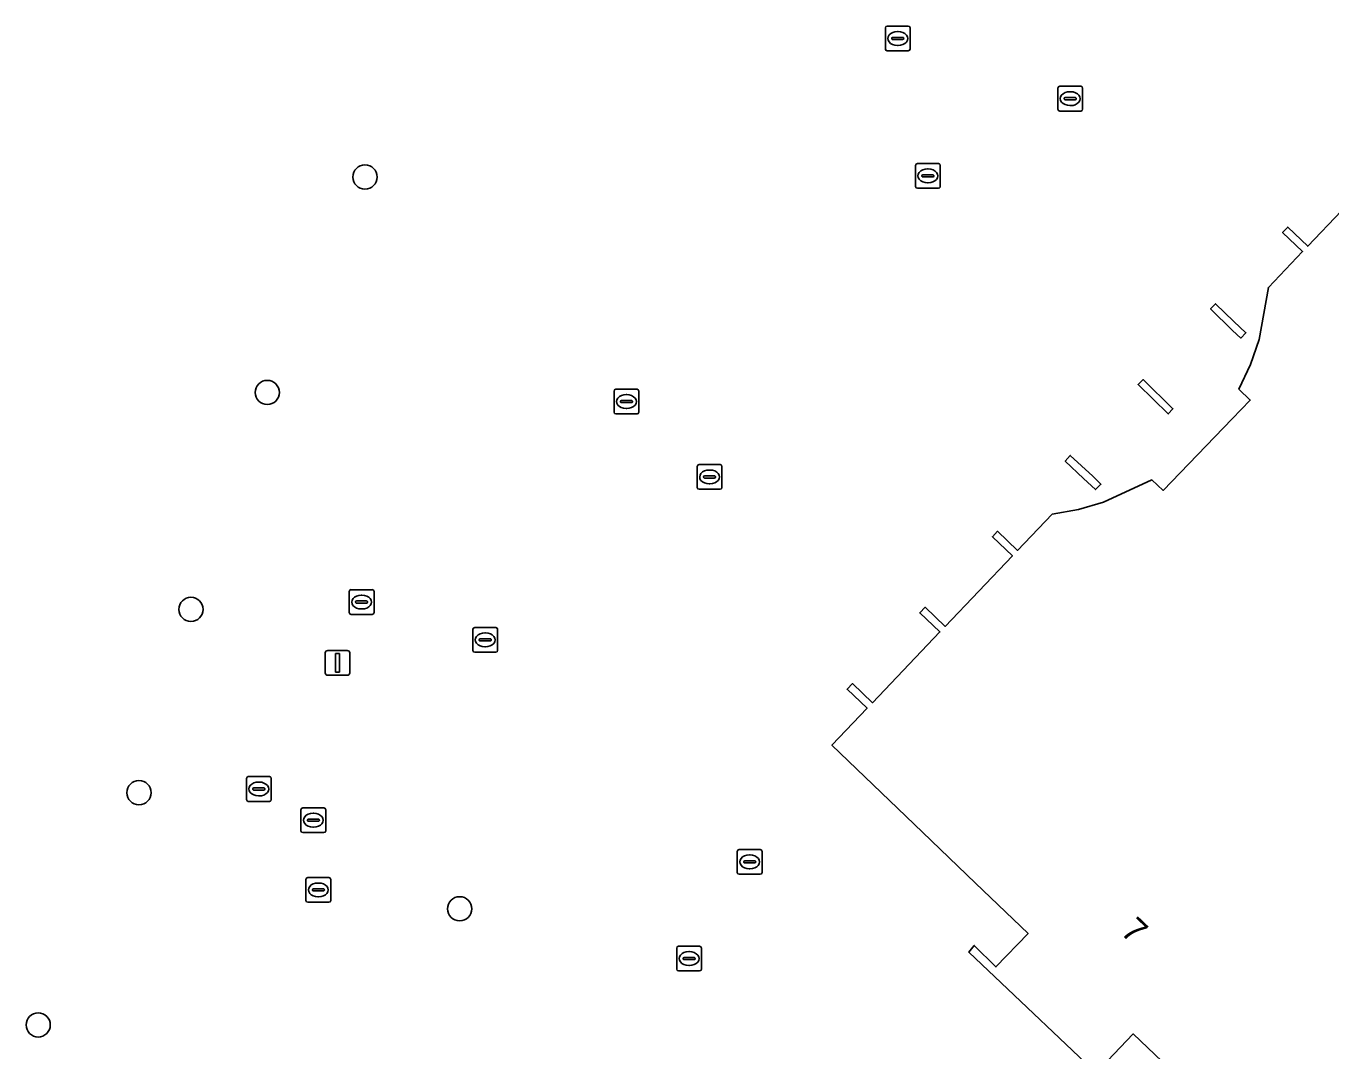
# Model space of a CAD drawing. Extents: x 156061 to 157804, y 383437 to 385640.
# Drawn here: x 156716.3 to 156769, y 385081.3 to 385122.7 of the extents above; entities that cross this region are included whole.
import ezdxf

# ---------------------------------------------------------------- set-up
doc = ezdxf.new("R2010")
doc.units = 0
for name, color, linetype in [('IMGEO_Boom', 7, 'Continuous'), ('IMGEO_Erf', 7, 'Continuous'), ('IMGEO_Kolk', 7, 'Continuous'), ('IMGEO_Lichtmast', 7, 'Continuous'), ('IMGEO_Pand', 7, 'Continuous'), ('IMGEO_Pand_nummerreeks', 7, 'Continuous'), ('IMGEO_Rioolput', 7, 'Continuous')]:
    doc.layers.add(name, color=color, linetype=linetype)

msp = doc.modelspace()

# ---------------------------------------------------------------- linework, layer by layer
at = {"layer": 'IMGEO_Boom'}
for centre in [(156730.004, 385116.568), (156726.055, 385107.866), (156722.969, 385099.103), (156720.871, 385091.698), (156733.83, 385087.008), (156716.798, 385082.318)]:
    msp.add_circle(centre, 0.489, dxfattribs=at)
at = {"layer": 'IMGEO_Erf'}
for points in [[(156760.425, 385079.549), (156754.405, 385085.261), (156754.626, 385085.527), (156755.503, 385084.662), (156756.803, 385086.009), (156754.676, 385088.049), (156752.53, 385090.107), (156748.874, 385093.614), (156750.296, 385095.106), (156749.486, 385095.879), (156749.699, 385096.103), (156750.509, 385095.33), (156753.234, 385098.19), (156752.424, 385098.963), (156752.638, 385099.187), (156753.448, 385098.414), (156756.166, 385101.267), (156755.356, 385102.04), (156755.563, 385102.257), (156756.373, 385101.484), (156757.769, 385102.949), (156758.836, 385103.138), (156759.851, 385103.431), (156761.8, 385104.331), (156762.254, 385103.908), (156762.945, 385104.624), (156765.052, 385106.806), (156765.778, 385107.557), (156765.322, 385107.998), (156765.792, 385108.99), (156766.141, 385110), (156766.514, 385112.109), (156767.894, 385113.558), (156767.083, 385114.331), (156767.29, 385114.548), (156768.101, 385113.775), (156770.825, 385116.635)], [(156768.968, 385074.402), (156761.046, 385081.957), (156759.76, 385080.603)]]:
    msp.add_lwpolyline(points, dxfattribs=at)
for points in [[(156765.401, 385110.061), (156765.065, 385110.37), (156764.175, 385111.241), (156764.37, 385111.451), (156765.12, 385110.733), (156765.605, 385110.279)], [(156761.243, 385108.182), (156761.444, 385108.383), (156762.656, 385107.209), (156762.467, 385106.999)], [(156758.303, 385105.094), (156758.501, 385105.323), (156759.413, 385104.478), (156759.74, 385104.157), (156759.526, 385103.94), (156759.041, 385104.39)]]:
    msp.add_lwpolyline(points, close=True, dxfattribs=at)
at = {"layer": 'IMGEO_Kolk'}
for p, q in [((156758.003, 385119.308), (156758.003, 385120.16)), ((156758.078, 385120.234), (156758.93, 385120.234)), ((156758.491, 385120.014), (156758.516, 385120.014)), ((156759.004, 385120.16), (156759.004, 385119.308)), ((156758.262, 385119.728), (156758.262, 385119.74)), ((156758.7, 385119.691), (156758.302, 385119.691)), ((156758.305, 385119.777), (156758.703, 385119.777)), ((156758.514, 385119.454), (156758.489, 385119.454)), ((156758.746, 385119.74), (156758.746, 385119.728)), ((156758.93, 385119.234), (156758.078, 385119.234)), ((156740.07, 385107.071), (156740.07, 385107.923)), ((156740.145, 385107.997), (156740.997, 385107.997)), ((156740.558, 385107.777), (156740.583, 385107.777)), ((156741.071, 385107.923), (156741.071, 385107.071)), ((156740.329, 385107.491), (156740.329, 385107.503)), ((156740.767, 385107.454), (156740.369, 385107.454)), ((156740.372, 385107.54), (156740.77, 385107.54)), ((156740.581, 385107.217), (156740.556, 385107.217)), ((156740.813, 385107.503), (156740.813, 385107.491)), ((156740.997, 385106.997), (156740.145, 385106.997)), ((156743.429, 385104.027), (156743.429, 385104.879)), ((156743.504, 385104.953), (156744.356, 385104.953)), ((156743.917, 385104.733), (156743.942, 385104.733)), ((156744.43, 385104.879), (156744.43, 385104.027)), ((156743.688, 385104.447), (156743.688, 385104.459)), ((156744.126, 385104.41), (156743.728, 385104.41)), ((156743.731, 385104.496), (156744.129, 385104.496)), ((156743.94, 385104.173), (156743.915, 385104.173)), ((156744.172, 385104.459), (156744.172, 385104.447)), ((156744.356, 385103.953), (156743.504, 385103.953)), ((156725.214, 385091.422), (156725.214, 385092.274)), ((156725.289, 385092.348), (156726.141, 385092.348)), ((156725.516, 385091.891), (156725.914, 385091.891)), ((156725.702, 385092.128), (156725.727, 385092.128)), ((156726.215, 385092.274), (156726.215, 385091.422)), ((156726.141, 385091.348), (156725.289, 385091.348)), ((156725.473, 385091.842), (156725.473, 385091.854)), ((156725.911, 385091.805), (156725.513, 385091.805)), ((156725.725, 385091.568), (156725.7, 385091.568)), ((156725.957, 385091.854), (156725.957, 385091.842)), ((156745.049, 385088.477), (156745.049, 385089.329)), ((156745.124, 385089.403), (156745.976, 385089.403)), ((156746.05, 385089.329), (156746.05, 385088.477)), ((156745.308, 385088.897), (156745.308, 385088.909)), ((156745.746, 385088.86), (156745.348, 385088.86)), ((156745.351, 385088.946), (156745.749, 385088.946)), ((156745.537, 385089.183), (156745.562, 385089.183)), ((156745.792, 385088.909), (156745.792, 385088.897)), ((156727.619, 385087.344), (156727.619, 385088.196)), ((156727.694, 385088.27), (156728.546, 385088.27)), ((156728.62, 385088.196), (156728.62, 385087.344)), ((156745.976, 385088.403), (156745.124, 385088.403)), ((156745.56, 385088.623), (156745.535, 385088.623)), ((156727.878, 385087.764), (156727.878, 385087.776)), ((156728.316, 385087.727), (156727.918, 385087.727)), ((156727.921, 385087.813), (156728.319, 385087.813)), ((156728.107, 385088.05), (156728.132, 385088.05)), ((156728.362, 385087.776), (156728.362, 385087.764)), ((156728.546, 385087.27), (156727.694, 385087.27)), ((156728.13, 385087.49), (156728.105, 385087.49)), ((156742.6, 385084.571), (156742.6, 385085.423)), ((156742.675, 385085.497), (156743.527, 385085.497)), ((156742.902, 385085.04), (156743.3, 385085.04)), ((156743.088, 385085.277), (156743.113, 385085.277)), ((156743.601, 385085.423), (156743.601, 385084.571)), ((156743.527, 385084.497), (156742.675, 385084.497)), ((156742.859, 385084.991), (156742.859, 385085.003)), ((156743.297, 385084.954), (156742.899, 385084.954)), ((156743.111, 385084.717), (156743.086, 385084.717)), ((156743.343, 385085.003), (156743.343, 385084.991))]:
    msp.add_line(p, q, dxfattribs=at)
for points in [[(156758.003, 385119.308), (156758.003, 385120.16)], [(156758.078, 385120.234), (156758.93, 385120.234)], [(156759.004, 385120.16), (156759.004, 385119.308)], [(156758.93, 385119.234), (156758.078, 385119.234)], [(156740.07, 385107.071), (156740.07, 385107.923)], [(156740.145, 385107.997), (156740.997, 385107.997)], [(156741.071, 385107.923), (156741.071, 385107.071)], [(156740.997, 385106.997), (156740.145, 385106.997)], [(156743.429, 385104.027), (156743.429, 385104.879)], [(156743.504, 385104.953), (156744.356, 385104.953)], [(156744.43, 385104.879), (156744.43, 385104.027)], [(156744.356, 385103.953), (156743.504, 385103.953)], [(156725.214, 385091.422), (156725.214, 385092.274)], [(156725.289, 385092.348), (156726.141, 385092.348)], [(156726.215, 385092.274), (156726.215, 385091.422)], [(156726.141, 385091.348), (156725.289, 385091.348)], [(156745.049, 385088.477), (156745.049, 385089.329)], [(156745.124, 385089.403), (156745.976, 385089.403)], [(156746.05, 385089.329), (156746.05, 385088.477)], [(156727.619, 385087.344), (156727.619, 385088.196)], [(156727.694, 385088.27), (156728.546, 385088.27)], [(156728.62, 385088.196), (156728.62, 385087.344)], [(156745.976, 385088.403), (156745.124, 385088.403)], [(156728.546, 385087.27), (156727.694, 385087.27)], [(156742.6, 385084.571), (156742.6, 385085.423)], [(156742.675, 385085.497), (156743.527, 385085.497)], [(156743.601, 385085.423), (156743.601, 385084.571)], [(156743.527, 385084.497), (156742.675, 385084.497)]]:
    msp.add_lwpolyline(points, dxfattribs=at)
for centre, radius, start, end in [((156758.08, 385120.158), 0.0765, 91.552, 178.448), ((156758.08, 385120.158), 0.0765, 91.552, 178.448), ((156758.928, 385120.158), 0.0765, 1.552, 88.448), ((156758.928, 385120.158), 0.0765, 1.552, 88.448), ((156758.08, 385119.31), 0.0765, 181.552, 268.448), ((156758.08, 385119.31), 0.0765, 181.552, 268.448), ((156758.302, 385119.737), 0.0403, 85.8775, 175.7526), ((156758.299, 385119.727), 0.0366, 178.938, 274.7102), ((156758.703, 385119.734), 0.043, 264.8664, 352.4533), ((156758.707, 385119.739), 0.0386, 1.7309, 96.639), ((156758.928, 385119.31), 0.0765, 271.552, 358.448), ((156758.928, 385119.31), 0.0765, 271.552, 358.448), ((156740.147, 385107.921), 0.0765, 91.552, 178.448), ((156740.147, 385107.921), 0.0765, 91.552, 178.448), ((156740.995, 385107.921), 0.0765, 1.552, 88.448), ((156740.995, 385107.921), 0.0765, 1.552, 88.448), ((156740.369, 385107.5), 0.0403, 85.8775, 175.7526), ((156740.366, 385107.49), 0.0366, 178.938, 274.7102), ((156740.77, 385107.497), 0.043, 264.8664, 352.4533), ((156740.774, 385107.502), 0.0386, 1.7309, 96.639), ((156740.147, 385107.073), 0.0765, 181.552, 268.448), ((156740.147, 385107.073), 0.0765, 181.552, 268.448), ((156740.995, 385107.073), 0.0765, 271.552, 358.448), ((156740.995, 385107.073), 0.0765, 271.552, 358.448), ((156743.506, 385104.877), 0.0765, 91.552, 178.448), ((156743.506, 385104.877), 0.0765, 91.552, 178.448), ((156744.354, 385104.877), 0.0765, 1.552, 88.448), ((156744.354, 385104.877), 0.0765, 1.552, 88.448), ((156743.506, 385104.029), 0.0765, 181.552, 268.448), ((156743.506, 385104.029), 0.0765, 181.552, 268.448), ((156743.728, 385104.456), 0.0403, 85.8775, 175.7526), ((156743.725, 385104.446), 0.0366, 178.938, 274.7102), ((156744.129, 385104.453), 0.043, 264.8664, 352.4533), ((156744.133, 385104.458), 0.0386, 1.7309, 96.639), ((156744.354, 385104.029), 0.0765, 271.552, 358.448), ((156744.354, 385104.029), 0.0765, 271.552, 358.448), ((156725.291, 385092.272), 0.0765, 91.552, 178.448), ((156725.291, 385092.272), 0.0765, 91.552, 178.448), ((156725.513, 385091.851), 0.0403, 85.8775, 175.7526), ((156725.918, 385091.853), 0.0386, 1.7309, 96.639), ((156726.139, 385092.272), 0.0765, 1.552, 88.448), ((156726.139, 385092.272), 0.0765, 1.552, 88.448), ((156725.291, 385091.424), 0.0765, 181.552, 268.448), ((156725.291, 385091.424), 0.0765, 181.552, 268.448), ((156725.51, 385091.841), 0.0366, 178.938, 274.7102), ((156725.914, 385091.848), 0.043, 264.8664, 352.4533), ((156726.139, 385091.424), 0.0765, 271.552, 358.448), ((156726.139, 385091.424), 0.0765, 271.552, 358.448), ((156745.126, 385089.327), 0.0765, 91.552, 178.448), ((156745.126, 385089.327), 0.0765, 91.552, 178.448), ((156745.974, 385089.327), 0.0765, 1.552, 88.448), ((156745.974, 385089.327), 0.0765, 1.552, 88.448), ((156745.348, 385088.906), 0.0403, 85.8775, 175.7526), ((156745.345, 385088.896), 0.0366, 178.938, 274.7102), ((156745.749, 385088.903), 0.043, 264.8664, 352.4533), ((156745.753, 385088.908), 0.0386, 1.7309, 96.639), ((156727.696, 385088.194), 0.0765, 91.552, 178.448), ((156727.696, 385088.194), 0.0765, 91.552, 178.448), ((156728.544, 385088.194), 0.0765, 1.552, 88.448), ((156728.544, 385088.194), 0.0765, 1.552, 88.448), ((156745.126, 385088.479), 0.0765, 181.552, 268.448), ((156745.126, 385088.479), 0.0765, 181.552, 268.448), ((156745.974, 385088.479), 0.0765, 271.552, 358.448), ((156745.974, 385088.479), 0.0765, 271.552, 358.448), ((156727.918, 385087.773), 0.0403, 85.8775, 175.7526), ((156727.915, 385087.763), 0.0366, 178.938, 274.7102), ((156728.319, 385087.77), 0.043, 264.8664, 352.4533), ((156728.323, 385087.775), 0.0386, 1.7309, 96.639), ((156727.696, 385087.346), 0.0765, 181.552, 268.448), ((156727.696, 385087.346), 0.0765, 181.552, 268.448), ((156728.544, 385087.346), 0.0765, 271.552, 358.448), ((156728.544, 385087.346), 0.0765, 271.552, 358.448), ((156742.677, 385085.421), 0.0765, 91.552, 178.448), ((156742.677, 385085.421), 0.0765, 91.552, 178.448), ((156742.899, 385085), 0.0403, 85.8775, 175.7526), ((156743.304, 385085.002), 0.0386, 1.7309, 96.639), ((156743.525, 385085.421), 0.0765, 1.552, 88.448), ((156743.525, 385085.421), 0.0765, 1.552, 88.448), ((156742.677, 385084.573), 0.0765, 181.552, 268.448), ((156742.677, 385084.573), 0.0765, 181.552, 268.448), ((156742.896, 385084.99), 0.0366, 178.938, 274.7102), ((156743.3, 385084.997), 0.043, 264.8664, 352.4533), ((156743.525, 385084.573), 0.0765, 271.552, 358.448), ((156743.525, 385084.573), 0.0765, 271.552, 358.448)]:
    msp.add_arc(centre, radius, start, end, dxfattribs=at)
for centre, major_axis, ratio, start_param, end_param in [((156758.49, 385119.734), (-0.387, 0.002), 0.722429, 4.712389, 7.853982), ((156758.515, 385119.734), (-0.39, 0.002), 0.717154, 1.570796, 4.712389), ((156740.557, 385107.497), (-0.387, 0.002), 0.722429, 4.712389, 7.853982), ((156740.582, 385107.497), (-0.39, 0.002), 0.717154, 1.570796, 4.712389), ((156743.916, 385104.453), (-0.387, 0.002), 0.722429, 4.712389, 7.853982), ((156743.941, 385104.453), (-0.39, 0.002), 0.717154, 1.570796, 4.712389), ((156725.701, 385091.848), (-0.387, 0.002), 0.722429, 4.712389, 7.853982), ((156725.726, 385091.848), (-0.39, 0.002), 0.717154, 1.570796, 4.712389), ((156745.536, 385088.903), (-0.387, 0.002), 0.722429, 4.712389, 7.853982), ((156745.561, 385088.903), (-0.39, 0.002), 0.717154, 1.570796, 4.712389), ((156728.106, 385087.77), (-0.387, 0.002), 0.722429, 4.712389, 7.853982), ((156728.131, 385087.77), (-0.39, 0.002), 0.717154, 1.570796, 4.712389), ((156743.087, 385084.997), (-0.387, 0.002), 0.722429, 4.712389, 7.853982), ((156743.112, 385084.997), (-0.39, 0.002), 0.717154, 1.570796, 4.712389)]:
    msp.add_ellipse(centre, major_axis=major_axis, ratio=ratio, start_param=start_param, end_param=end_param, dxfattribs=at)
at = {"layer": 'IMGEO_Lichtmast'}
for p, q in [((156728.398, 385096.543), (156728.398, 385097.343)), ((156728.398, 385097.343), (156728.398, 385096.543)), ((156728.498, 385097.443), (156729.288, 385097.443)), ((156729.288, 385097.443), (156728.498, 385097.443)), ((156729.388, 385097.343), (156729.388, 385096.543)), ((156729.388, 385096.543), (156729.388, 385097.343)), ((156729.288, 385096.443), (156728.498, 385096.443)), ((156728.498, 385096.443), (156729.288, 385096.443))]:
    msp.add_line(p, q, dxfattribs=at)
msp.add_lwpolyline([(156728.818, 385097.318), (156728.968, 385097.318), (156728.968, 385096.568), (156728.818, 385096.568), (156728.818, 385097.318)], dxfattribs=at)
for centre, start, end in [((156728.498, 385097.343), 90, 180), ((156728.498, 385097.343), 90, 180), ((156729.288, 385097.343), 0, 90), ((156729.288, 385097.343), 360, 90), ((156728.498, 385096.543), 180, 270), ((156728.498, 385096.543), 180, 270), ((156729.288, 385096.543), 270, 0), ((156729.288, 385096.543), 270, 0)]:
    msp.add_arc(centre, 0.1, start, end, dxfattribs=at)
at = {"layer": 'IMGEO_Pand'}
for points in [[(156770.825, 385116.635), (156768.101, 385113.775), (156767.29, 385114.548), (156767.083, 385114.331), (156767.894, 385113.558), (156766.514, 385112.109), (156766.141, 385110), (156765.792, 385108.99), (156765.322, 385107.998), (156765.778, 385107.557), (156765.052, 385106.806), (156762.945, 385104.624), (156762.254, 385103.908), (156761.8, 385104.331), (156759.851, 385103.431), (156758.836, 385103.138), (156757.769, 385102.949), (156756.373, 385101.484), (156755.563, 385102.257), (156755.356, 385102.04), (156756.166, 385101.267), (156753.448, 385098.414), (156752.638, 385099.187), (156752.424, 385098.963), (156753.234, 385098.19), (156750.509, 385095.33), (156749.699, 385096.103), (156749.486, 385095.879), (156750.296, 385095.106), (156748.874, 385093.614), (156752.53, 385090.107), (156754.676, 385088.049), (156756.803, 385086.009), (156755.503, 385084.662), (156754.626, 385085.527), (156754.405, 385085.261), (156760.425, 385079.549)], [(156759.76, 385080.603), (156761.046, 385081.957), (156768.968, 385074.402)]]:
    msp.add_lwpolyline(points, dxfattribs=at)
for points in [[(156765.12, 385110.733), (156764.37, 385111.451), (156764.175, 385111.241), (156765.065, 385110.37), (156765.401, 385110.061), (156765.605, 385110.279)], [(156762.467, 385106.999), (156762.656, 385107.209), (156761.444, 385108.383), (156761.243, 385108.182)], [(156759.041, 385104.39), (156759.526, 385103.94), (156759.74, 385104.157), (156759.413, 385104.478), (156758.501, 385105.323), (156758.303, 385105.094)]]:
    msp.add_lwpolyline(points, close=True, dxfattribs=at)
at = {"layer": 'IMGEO_Rioolput'}
for p, q in [((156751.033, 385121.738), (156751.033, 385122.59)), ((156751.108, 385122.664), (156751.96, 385122.664)), ((156752.034, 385122.59), (156752.034, 385121.738)), ((156751.292, 385122.158), (156751.292, 385122.17)), ((156751.73, 385122.121), (156751.332, 385122.121)), ((156751.335, 385122.207), (156751.733, 385122.207)), ((156751.521, 385122.444), (156751.546, 385122.444)), ((156751.776, 385122.17), (156751.776, 385122.158)), ((156751.96, 385121.664), (156751.108, 385121.664)), ((156751.544, 385121.884), (156751.519, 385121.884)), ((156752.251, 385116.188), (156752.251, 385117.04)), ((156752.326, 385117.114), (156753.178, 385117.114)), ((156752.553, 385116.657), (156752.951, 385116.657)), ((156752.739, 385116.894), (156752.764, 385116.894)), ((156753.252, 385117.04), (156753.252, 385116.188)), ((156752.51, 385116.608), (156752.51, 385116.62)), ((156752.948, 385116.571), (156752.55, 385116.571)), ((156752.762, 385116.334), (156752.737, 385116.334)), ((156752.994, 385116.62), (156752.994, 385116.608)), ((156753.178, 385116.114), (156752.326, 385116.114)), ((156729.367, 385098.973), (156729.367, 385099.825)), ((156729.442, 385099.899), (156730.294, 385099.899)), ((156730.368, 385099.825), (156730.368, 385098.973)), ((156729.626, 385099.393), (156729.626, 385099.405)), ((156730.064, 385099.356), (156729.666, 385099.356)), ((156729.669, 385099.442), (156730.067, 385099.442)), ((156729.855, 385099.679), (156729.88, 385099.679)), ((156730.11, 385099.405), (156730.11, 385099.393)), ((156730.294, 385098.899), (156729.442, 385098.899)), ((156729.878, 385099.119), (156729.853, 385099.119)), ((156734.361, 385097.446), (156734.361, 385098.298)), ((156734.436, 385098.372), (156735.288, 385098.372)), ((156735.362, 385098.298), (156735.362, 385097.446)), ((156734.62, 385097.866), (156734.62, 385097.878)), ((156735.058, 385097.829), (156734.66, 385097.829)), ((156734.663, 385097.915), (156735.061, 385097.915)), ((156734.849, 385098.152), (156734.874, 385098.152)), ((156735.104, 385097.878), (156735.104, 385097.866)), ((156735.288, 385097.372), (156734.436, 385097.372)), ((156734.872, 385097.592), (156734.847, 385097.592)), ((156727.417, 385090.16), (156727.417, 385091.012)), ((156727.492, 385091.086), (156728.344, 385091.086)), ((156727.905, 385090.866), (156727.93, 385090.866)), ((156728.418, 385091.012), (156728.418, 385090.16)), ((156727.676, 385090.58), (156727.676, 385090.592)), ((156728.114, 385090.543), (156727.716, 385090.543)), ((156727.719, 385090.629), (156728.117, 385090.629)), ((156727.928, 385090.306), (156727.903, 385090.306)), ((156728.16, 385090.592), (156728.16, 385090.58)), ((156728.344, 385090.086), (156727.492, 385090.086))]:
    msp.add_line(p, q, dxfattribs=at)
for points in [[(156751.033, 385121.738), (156751.033, 385122.59)], [(156751.108, 385122.664), (156751.96, 385122.664)], [(156752.034, 385122.59), (156752.034, 385121.738)], [(156751.96, 385121.664), (156751.108, 385121.664)], [(156752.251, 385116.188), (156752.251, 385117.04)], [(156752.326, 385117.114), (156753.178, 385117.114)], [(156753.252, 385117.04), (156753.252, 385116.188)], [(156753.178, 385116.114), (156752.326, 385116.114)], [(156729.367, 385098.973), (156729.367, 385099.825)], [(156729.442, 385099.899), (156730.294, 385099.899)], [(156730.368, 385099.825), (156730.368, 385098.973)], [(156730.294, 385098.899), (156729.442, 385098.899)], [(156734.361, 385097.446), (156734.361, 385098.298)], [(156734.436, 385098.372), (156735.288, 385098.372)], [(156735.362, 385098.298), (156735.362, 385097.446)], [(156735.288, 385097.372), (156734.436, 385097.372)], [(156727.417, 385090.16), (156727.417, 385091.012)], [(156727.492, 385091.086), (156728.344, 385091.086)], [(156728.418, 385091.012), (156728.418, 385090.16)], [(156728.344, 385090.086), (156727.492, 385090.086)]]:
    msp.add_lwpolyline(points, dxfattribs=at)
for centre, radius, start, end in [((156751.11, 385122.588), 0.0765, 91.552, 178.448), ((156751.11, 385122.588), 0.0765, 91.552, 178.448), ((156751.958, 385122.588), 0.0765, 1.552, 88.448), ((156751.958, 385122.588), 0.0765, 1.552, 88.448), ((156751.332, 385122.167), 0.0403, 85.8775, 175.7526), ((156751.329, 385122.157), 0.0366, 178.938, 274.7102), ((156751.733, 385122.164), 0.043, 264.8664, 352.4533), ((156751.737, 385122.169), 0.0386, 1.7309, 96.639), ((156751.11, 385121.74), 0.0765, 181.552, 268.448), ((156751.11, 385121.74), 0.0765, 181.552, 268.448), ((156751.958, 385121.74), 0.0765, 271.552, 358.448), ((156751.958, 385121.74), 0.0765, 271.552, 358.448), ((156752.328, 385117.038), 0.0765, 91.552, 178.448), ((156752.328, 385117.038), 0.0765, 91.552, 178.448), ((156752.55, 385116.617), 0.0403, 85.8775, 175.7526), ((156752.955, 385116.619), 0.0386, 1.7309, 96.639), ((156753.176, 385117.038), 0.0765, 1.552, 88.448), ((156753.176, 385117.038), 0.0765, 1.552, 88.448), ((156752.328, 385116.19), 0.0765, 181.552, 268.448), ((156752.328, 385116.19), 0.0765, 181.552, 268.448), ((156752.547, 385116.607), 0.0366, 178.938, 274.7102), ((156752.951, 385116.614), 0.043, 264.8664, 352.4533), ((156753.176, 385116.19), 0.0765, 271.552, 358.448), ((156753.176, 385116.19), 0.0765, 271.552, 358.448), ((156729.444, 385099.823), 0.0765, 91.552, 178.448), ((156729.444, 385099.823), 0.0765, 91.552, 178.448), ((156730.292, 385099.823), 0.0765, 1.552, 88.448), ((156730.292, 385099.823), 0.0765, 1.552, 88.448), ((156729.666, 385099.402), 0.0403, 85.8775, 175.7526), ((156729.663, 385099.392), 0.0366, 178.938, 274.7102), ((156730.067, 385099.399), 0.043, 264.8664, 352.4533), ((156730.071, 385099.404), 0.0386, 1.7309, 96.639), ((156729.444, 385098.975), 0.0765, 181.552, 268.448), ((156729.444, 385098.975), 0.0765, 181.552, 268.448), ((156730.292, 385098.975), 0.0765, 271.552, 358.448), ((156730.292, 385098.975), 0.0765, 271.552, 358.448), ((156734.438, 385098.296), 0.0765, 91.552, 178.448), ((156734.438, 385098.296), 0.0765, 91.552, 178.448), ((156735.286, 385098.296), 0.0765, 1.552, 88.448), ((156735.286, 385098.296), 0.0765, 1.552, 88.448), ((156734.66, 385097.875), 0.0403, 85.8775, 175.7526), ((156734.657, 385097.865), 0.0366, 178.938, 274.7102), ((156735.061, 385097.872), 0.043, 264.8664, 352.4533), ((156735.065, 385097.877), 0.0386, 1.7309, 96.639), ((156734.438, 385097.448), 0.0765, 181.552, 268.448), ((156734.438, 385097.448), 0.0765, 181.552, 268.448), ((156735.286, 385097.448), 0.0765, 271.552, 358.448), ((156735.286, 385097.448), 0.0765, 271.552, 358.448), ((156727.494, 385091.01), 0.0765, 91.552, 178.448), ((156727.494, 385091.01), 0.0765, 91.552, 178.448), ((156728.342, 385091.01), 0.0765, 1.552, 88.448), ((156728.342, 385091.01), 0.0765, 1.552, 88.448), ((156727.716, 385090.589), 0.0403, 85.8775, 175.7526), ((156727.713, 385090.579), 0.0366, 178.938, 274.7102), ((156728.117, 385090.586), 0.043, 264.8664, 352.4533), ((156728.121, 385090.591), 0.0386, 1.7309, 96.639), ((156727.494, 385090.162), 0.0765, 181.552, 268.448), ((156727.494, 385090.162), 0.0765, 181.552, 268.448), ((156728.342, 385090.162), 0.0765, 271.552, 358.448), ((156728.342, 385090.162), 0.0765, 271.552, 358.448)]:
    msp.add_arc(centre, radius, start, end, dxfattribs=at)
for centre, major_axis, ratio, start_param, end_param in [((156751.52, 385122.164), (-0.387, 0.002), 0.722429, 4.712389, 7.853982), ((156751.545, 385122.164), (-0.39, 0.002), 0.717154, 1.570796, 4.712389), ((156752.738, 385116.614), (-0.387, 0.002), 0.722429, 4.712389, 7.853982), ((156752.763, 385116.614), (-0.39, 0.002), 0.717154, 1.570796, 4.712389), ((156729.854, 385099.399), (-0.387, 0.002), 0.722429, 4.712389, 7.853982), ((156729.879, 385099.399), (-0.39, 0.002), 0.717154, 1.570796, 4.712389), ((156734.848, 385097.872), (-0.387, 0.002), 0.722429, 4.712389, 7.853982), ((156734.873, 385097.872), (-0.39, 0.002), 0.717154, 1.570796, 4.712389), ((156727.904, 385090.586), (-0.387, 0.002), 0.722429, 4.712389, 7.853982), ((156727.929, 385090.586), (-0.39, 0.002), 0.717154, 1.570796, 4.712389)]:
    msp.add_ellipse(centre, major_axis=major_axis, ratio=ratio, start_param=start_param, end_param=end_param, dxfattribs=at)

# ---------------------------------------------------------------- texts
at = {"layer": 'IMGEO_Pand_nummerreeks'}
msp.add_text('7', height=1, rotation=316.3568, dxfattribs=at).set_placement((156760.493, 385086.032))

doc.saveas('drawing.dxf')
